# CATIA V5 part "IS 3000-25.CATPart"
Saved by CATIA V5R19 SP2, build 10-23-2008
Part number: IS 3000-25
Bounding box of the stored display mesh (mm): x -47.487 to 47.487, y -47.487 to 47.487, z 0 to 170
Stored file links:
  C:\Users\Bora\Desktop\3D Katı model\IS serisi\IS 3000\IS 3000-25.CATPart
  C:\Program Files\Dassault Systemes\B19\intel_a\reffiles\standard\MetricThickPitch.txt
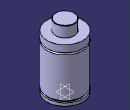
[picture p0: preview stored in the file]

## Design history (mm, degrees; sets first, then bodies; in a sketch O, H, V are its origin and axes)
Body1 (main body)
  Sketch1 on yz-plane, origin (0, 0, 0), H (0, 1, 0), V (0, 0, 1)
    point P1 (47.5, 123.5)
    point P2 (47.5, 118.5)
    point P5 (25, 169)
    point P7 (25, 169)
    point P12 (47.5, 118.5)
    point P13 (47.5, 123.5)
    arc A1 centre (47.5, 121) radius 2.5 from (47.5, 123.5) to (47.5, 118.5) ccw
    line L1 (47.5, 0) -> (47.5, 8)
    line L2 (25, 169) -> (25, 142)
    arc A2 centre (24, 169) radius 1 from (25, 169) to (24, 170) ccw
    line L3 (43.5, 13) -> (43.5, 8)
    line L4 (47.5, 13) -> (47.5, 118.5)
    line L5 (47.5, 123.5) -> (47.5, 142)
    line L6 (24, 170) -> (0, 170)
    point P15 (0, 170)
    line L7 (25, 142) -> (47.5, 142)
    line L8 (0, 0) -> (47.5, 0)
    line L9 (43.5, 13) -> (47.5, 13)
    line L10 (43.5, 8) -> (47.5, 8)
    coincidence: P15 V, P1 P13, P2 P12, P5 P7
    tangency: L6 A2
    horizontal: L7 H, L8 H, L9 H, L10 H
  Shaft1: profile Sketch1, axis Sketch1.V, angle 360
  Sketch2 on face of Shaft1 from Sketch1.L8, origin (0, 0, 0), H (1, 0, 0), V (0, -1, 0)
    point P1 (30, 0)
    distance P1 V = 30
  Hole1: placed by Sketch2, at (30, 0, 0) direction (0, 0, 1), diameter 6.647, depth 13, threaded "M8", thread diameter 8, thread depth 13, pitch 1.25
  CircPattern1: of Hole1, instances 4, angular step 90, axis from xy-plane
